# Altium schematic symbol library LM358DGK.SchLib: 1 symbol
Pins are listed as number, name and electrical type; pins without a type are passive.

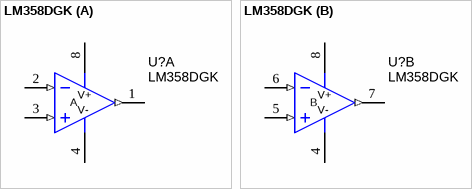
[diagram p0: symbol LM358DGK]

## LM358DGK
designator U?
Low Power Dual Op Amp; CompType: OpAmp IC
footprint DGK0008A_L (TSOP, 8-Leads, Body 3x3mm, Pitch 0.65mm, IPC High Density)
footprint DGK0008A_M (TSOP, 8-Leads, Body 3x3mm, Pitch 0.65mm, IPC Low Density)
footprint DGK0008A_N (TSOP, 8-Leads, Body 3x3mm, Pitch 0.65mm, IPC Medium Density)
simulation model LM358 (SUBCKT)
pins on every part: 4 V- (power), 8 V+ (power)
part A pins: 1 OUT (out), 2 IN- (in), 3 IN+ (in)
part B pins: 5 IN+ (in), 6 IN- (in), 7 OUT (out)
3 alternate drawings of the same symbol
